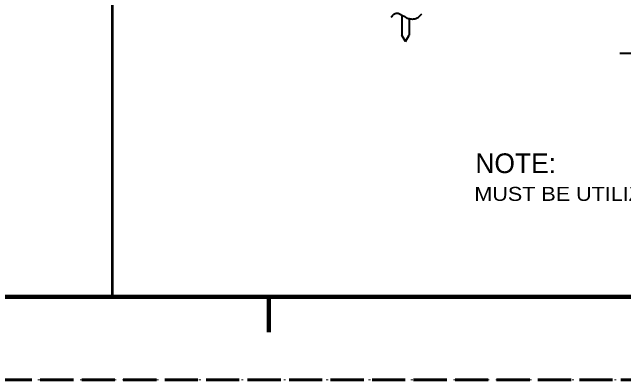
# Model space of a CAD drawing. Extents: x 312583 to 312854, y 144419 to 144597.
# Drawn here: x 312713.43 to 312746.6, y 144418.58 to 144438.54 of the extents above; entities that cross this region are included whole.
import ezdxf
from ezdxf.enums import TextEntityAlignment as Align

# ---------------------------------------------------------------- set-up
doc = ezdxf.new("R2010")
doc.units = 0
doc.header["$LTSCALE"] = 0.3
doc.linetypes.add('DOTTED', pattern=[1.5, 0.3, -1.2])
doc.linetypes.add('LONG_DASHED', pattern=[7.5, 6, -1.5])
for name, color, linetype, lineweight in [('1', 7, 'Continuous', 25), ('2', 7, 'Continuous', 13), ('63', 7, 'DOTTED', 13)]:
    doc.layers.add(name, color=color, linetype=linetype, lineweight=lineweight)

msp = doc.modelspace()

# ---------------------------------------------------------------- linework, layer by layer
at = {"layer": '1', "lineweight": 53}
msp.add_line((312718.861, 144423.0846), (312718.861, 144506.4889), dxfattribs=at)
at = {"layer": '1', "lineweight": 40}
for p, q in [((312734.5682, 144438.3775), (312734.5682, 144437.2888)), ((312734.9669, 144438.2011), (312734.9669, 144437.2888)), ((312734.7676, 144436.9438), (312734.5682, 144437.2888)), ((312734.7676, 144436.9438), (312734.9669, 144437.2888))]:
    msp.add_line(p, q, dxfattribs=at)
at = {"layer": '1', "lineweight": 158}
for p, q in [((312616.5, 144423.0846), (312849, 144423.0846)), ((312727.35, 144421.1646), (312727.35, 144423.0846))]:
    msp.add_line(p, q, dxfattribs=at)
at = {"layer": '1', "linetype": 'LONG_DASHED', "lineweight": 60}
msp.add_line((312851.75, 144418.5846), (312583.526, 144418.5846), dxfattribs=at)
at = {"layer": '1', "lineweight": 40}
msp.add_spline([(312733.9856, 144438.2625), (312734.1389, 144438.4311), (312734.2922, 144438.4925), (312734.4379, 144438.4541), (312734.5682, 144438.3775), (312734.7216, 144438.3008), (312734.8366, 144438.2241), (312735.0052, 144438.1858), (312735.1356, 144438.1705), (312735.2659, 144438.1858), (312735.5112, 144438.3008), (312735.6416, 144438.4541)], degree=3, dxfattribs=at)
at = {"layer": '2', "lineweight": 40}
msp.add_line((312746.3902, 144436.3151), (312777.4709, 144436.3151), dxfattribs=at)
at = {"layer": '63'}
msp.add_lwpolyline([(312601.2, 144418.5846), (312853.5, 144418.5846), (312853.5, 144596.7846)], dxfattribs=at)

# ---------------------------------------------------------------- texts
at = {"layer": '2'}
msp.add_text('NOTE:', height=1.07, dxfattribs=at).set_placement((312740.7399, 144429.8049), align=Align.CENTER)
at = {"layer": '2', "width": 1.15}
msp.add_text('MUST BE UTILIZED WHEN RAINTIGHT DISCONNECT IS REQUIRED', height=0.76, dxfattribs=at).set_placement((312738.4984, 144428.2971))

doc.saveas('drawing.dxf')
